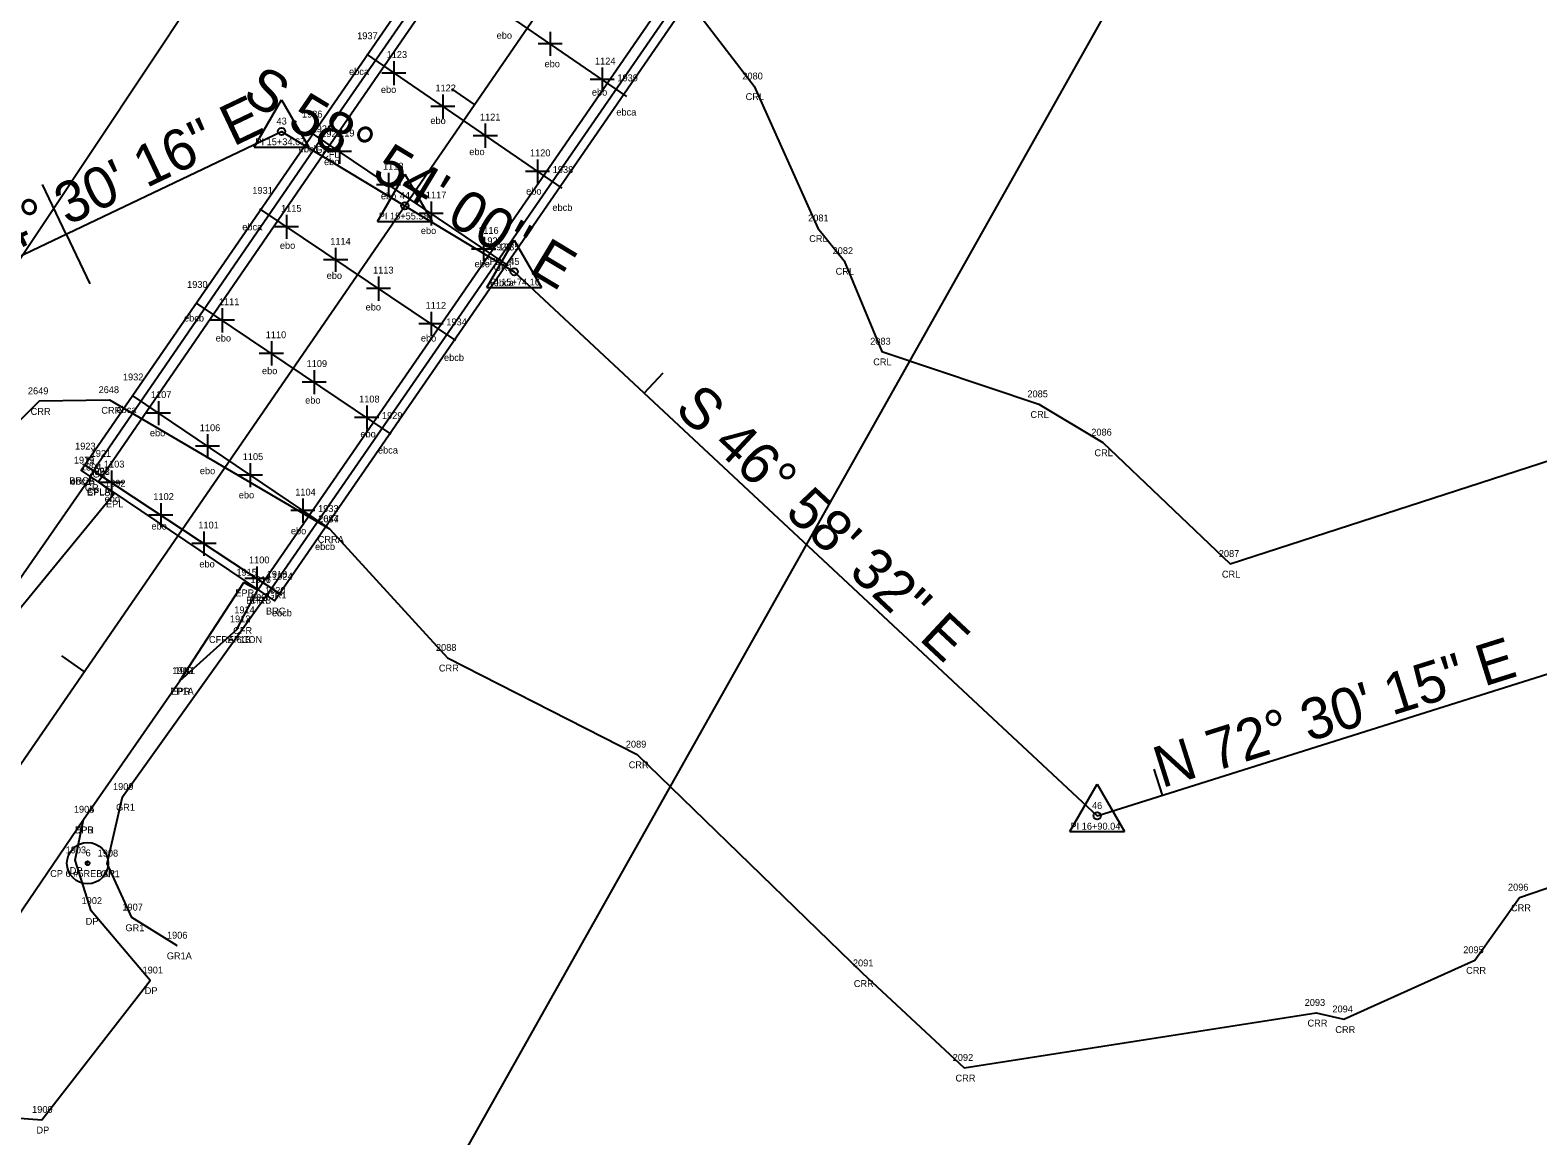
# Model space of a CAD drawing. Extents: x 2266664 to 2272542, y 716533 to 724777.
# Drawn here: x 2269953.4 to 2270172.5, y 721208.7 to 721369.4 of the extents above; entities that cross this region are included whole.
import ezdxf

# ---------------------------------------------------------------- set-up
doc = ezdxf.new("R2010")
doc.units = 0
for name, color, linetype in [('RD_EX_Bridge', 7, 'Continuous'), ('RD_EX_Bridge_txCode', 7, 'Continuous'), ('RD_EX_Conc', 7, 'Continuous'), ('RD_EX_Conc_txCode', 7, 'Continuous'), ('RD_EX_Driveway', 7, 'Continuous'), ('RD_EX_Driveway_txCode', 7, 'Continuous'), ('RD_EX_GuardRail', 7, 'Continuous'), ('RD_EX_GuardRail_txCode', 7, 'Continuous'), ('RD_EX_H2O', 7, 'Continuous'), ('RD_EX_H2O_txCode', 7, 'Continuous'), ('RD_EX_Misc', 7, 'Continuous'), ('RD_EX_Misc_txCode', 7, 'Continuous'), ('RD_EX_Road', 7, 'Continuous'), ('RD_EX_Road_txCode', 7, 'Continuous'), ('RD_EX_VEG', 7, 'Continuous'), ('RD_HC_Cl', 7, 'Continuous'), ('RD_HC_Data', 7, 'Continuous'), ('RD_HC_Data_Tic', 7, 'Continuous'), ('RD_HC_txCode', 7, 'Continuous'), ('RD_SMD_Locator', 7, 'Continuous')]:
    doc.layers.add(name, color=color, linetype=linetype)

msp = doc.modelspace()

# ---------------------------------------------------------------- linework, layer by layer
at = {"layer": 'RD_EX_Bridge'}
msp.add_lwpolyline([(2269960.85, 721305.41), (2269988.95, 721286.47), (2270056.9, 721385.08), (2270029.02, 721404.36), (2269960.85, 721305.41)], dxfattribs=at)
at = {"layer": 'RD_EX_Conc'}
for points in [[(2269963.38, 721303.82), (2269997.07, 721352.85), (2270031.4, 721402.66), (2270033.2, 721405.68), (2270033.91, 721407.54)], [(2269983.54, 721282.33), (2269984.17, 721283.64), (2269986.54, 721288.04), (2270020.48, 721337.28), (2270054.42, 721386.58), (2270057.31, 721390.25), (2270060.54, 721392.95), (2270061.95, 721393.64)]]:
    msp.add_lwpolyline(points, dxfattribs=at)
at = {"layer": 'RD_EX_Driveway'}
msp.add_lwpolyline([(2269930.38, 721209.38), (2269942.85, 721211.94), (2269955.14, 721211.05), (2269970.87, 721231.31), (2269962.29, 721241.39), (2269959.97, 721248.76), (2269961.18, 721254.67)], dxfattribs=at)
at = {"layer": 'RD_EX_GuardRail'}
for points in [[(2269870.57, 721186.54), (2269949.59, 721286.31), (2269962.16, 721304.4), (2269963.29, 721306.38), (2269995.7, 721353.55), (2270029.01, 721401.69), (2270040.18, 721416.99), (2270068.93, 721465.92)], [(2269974.73, 721236.37), (2269968.22, 721240.45), (2269964.64, 721248.3), (2269966.87, 721257.97), (2269988.88, 721288.81), (2270021.75, 721336.4), (2270054.42, 721383.83), (2270066.31, 721401.03), (2270101.34, 721444.56)]]:
    msp.add_lwpolyline(points, dxfattribs=at)
at = {"layer": 'RD_EX_H2O'}
for points in [[(2270050.62, 721371.69), (2270058.64, 721361.22), (2270067.88, 721340.59), (2270071.72, 721335.84), (2270077.18, 721322.68), (2270100.02, 721315.03), (2270109.33, 721309.47), (2270127.84, 721291.83), (2270185.1, 721310.38), (2270243.87, 721304.44), (2270281.75, 721346.08), (2270379.45, 721379), (2270436.63, 721386.23), (2270462.17, 721399.02)], [(2269996.97, 721296.88), (2269965.03, 721315.64), (2269954.76, 721315.47), (2269929.78, 721290.65), (2269924.59, 721291.58), (2269907.47, 721298.96), (2269898.39, 721300.95), (2269889.07, 721317.1), (2269874.61, 721338.02), (2269854.27, 721369.2), (2269839.08, 721382.01), (2269832.71, 721368.75), (2269810.27, 721357.54), (2269761.21, 721366.63), (2269754.56, 721317.04), (2269765.82, 721305.79), (2269769.06, 721297.52)], [(2269996.97, 721296.88), (2270014.08, 721278.19), (2270041.67, 721264.13), (2270074.38, 721232.34), (2270089.16, 721218.61), (2270140.31, 721226.6), (2270144.35, 721225.65), (2270163.36, 721234.25), (2270169.88, 721243.35), (2270177.39, 721245.92), (2270182.44, 721236.62), (2270238.2, 721231.39), (2270303.78, 721285.16), (2270310.34, 721288.45), (2270391.6, 721320.78), (2270477.31, 721344.54)]]:
    msp.add_lwpolyline(points, dxfattribs=at)
at = {"layer": 'RD_EX_Misc'}
for p, q in [((2270040.13, 721359.75), (2270011.59, 721379.34)), ((2270030.75, 721367.39), (2270027.25, 721367.39)), ((2270029, 721369.14), (2270029, 721365.64)), ((2270002.31, 721365.87), (2270030.72, 721346.42)), ((2270008.05, 721363.14), (2270004.55, 721363.14)), ((2270006.3, 721364.89), (2270006.3, 721361.39)), ((2270036.58, 721363.94), (2270036.58, 721360.44)), ((2270038.33, 721362.19), (2270034.83, 721362.19)), ((2270013.4, 721360.03), (2270013.4, 721356.53)), ((2270015.15, 721358.28), (2270011.65, 721358.28)), ((2270022.91, 721335.17), (2269994.31, 721354.48)), ((2270021.33, 721354.05), (2270017.83, 721354.05)), ((2270019.58, 721355.8), (2270019.58, 721352.3)), ((2269998.37, 721353.48), (2269998.37, 721349.98)), ((2270000.12, 721351.73), (2269996.62, 721351.73)), ((2270027.18, 721350.6), (2270027.18, 721347.1)), ((2270005.5, 721348.67), (2270005.5, 721345.17)), ((2270028.93, 721348.85), (2270025.43, 721348.85)), ((2270007.25, 721346.92), (2270003.75, 721346.92)), ((2269986.79, 721343.4), (2270015.26, 721324.29)), ((2270011.72, 721344.48), (2270011.72, 721340.98)), ((2269990.68, 721342.54), (2269990.68, 721339.04)), ((2270013.47, 721342.73), (2270009.97, 721342.73)), ((2269992.43, 721340.79), (2269988.93, 721340.79)), ((2270019.34, 721339.33), (2270019.34, 721335.83)), ((2269997.83, 721337.75), (2269997.83, 721334.25)), ((2270021.09, 721337.58), (2270017.59, 721337.58)), ((2269999.58, 721336), (2269996.08, 721336)), ((2270004.05, 721333.57), (2270004.05, 721330.07)), ((2270005.8, 721331.82), (2270002.3, 721331.82)), ((2270005.91, 721310.68), (2269977.63, 721329.73)), ((2269981.36, 721328.97), (2269981.36, 721325.47)), ((2270011.69, 721328.44), (2270011.69, 721324.94)), ((2269983.11, 721327.22), (2269979.61, 721327.22)), ((2270013.44, 721326.69), (2270009.94, 721326.69)), ((2269988.49, 721324.17), (2269988.49, 721320.67)), ((2269990.24, 721322.42), (2269986.74, 721322.42)), ((2269994.71, 721319.98), (2269994.71, 721316.48)), ((2269996.46, 721318.23), (2269992.96, 721318.23)), ((2269968.27, 721316.29), (2269996.62, 721297.16)), ((2269972.09, 721315.47), (2269972.09, 721311.97)), ((2270002.34, 721314.83), (2270002.34, 721311.33)), ((2269973.84, 721313.72), (2269970.34, 721313.72)), ((2270004.09, 721313.08), (2270000.59, 721313.08)), ((2269979.22, 721310.66), (2269979.22, 721307.16)), ((2269980.97, 721308.91), (2269977.47, 721308.91)), ((2269961.32, 721306.24), (2269989.97, 721287.33)), ((2269985.43, 721306.46), (2269985.43, 721302.96)), ((2269967.02, 721303.63), (2269963.52, 721303.63)), ((2269965.27, 721305.38), (2269965.27, 721301.88)), ((2269987.18, 721304.71), (2269983.68, 721304.71)), ((2269972.44, 721300.65), (2269972.44, 721297.15)), ((2269994.81, 721299.56), (2269991.31, 721299.56)), ((2269993.06, 721301.31), (2269993.06, 721297.81)), ((2269974.19, 721298.9), (2269970.69, 721298.9)), ((2269978.7, 721296.52), (2269978.7, 721293.02)), ((2269980.45, 721294.77), (2269976.95, 721294.77)), ((2269986.38, 721291.45), (2269986.38, 721287.95)), ((2269988.13, 721289.7), (2269984.63, 721289.7))]:
    msp.add_line(p, q, dxfattribs=at)
at = {"layer": 'RD_EX_Road'}
msp.add_line((2269975.2, 721274.82), (2269983.54, 721282.33), dxfattribs=at)
for points in [[(2269202.93, 720196.07), (2269237.22, 720244.72), (2269259.4, 720276.99), (2269259.41, 720277.21), (2269317.32, 720361.94), (2269369.05, 720437.36), (2269428.45, 720522.87), (2269487.41, 720608.15), (2269502.81, 720630.76), (2269544.96, 720692.14), (2269605.63, 720780.46), (2269663.95, 720865.82), (2269721.16, 720948.73), (2269780.45, 721034.57), (2269834.47, 721112.56), (2269853.48, 721140.68), (2269880.91, 721180.54), (2269894.87, 721200.75), (2269951.76, 721285.08), (2269965.67, 721302.04), (2269963.39, 721303.74)], [(2269222.47, 720182.37), (2269278.1, 720262.57), (2269277.83, 720263.03), (2269337.43, 720348.71), (2269393.72, 720430.44), (2269448.55, 720510.19), (2269506.62, 720593.92), (2269564.83, 720678.53), (2269625.78, 720767.57), (2269683.68, 720852.02), (2269741.8, 720936.18), (2269800.12, 721020.89), (2269854.32, 721099.54), (2269879.26, 721135.52), (2269912.84, 721184.64), (2269930.38, 721209.38), (2269961.18, 721254.67), (2269975.2, 721274.82), (2269984.48, 721289.11), (2269986.54, 721288.04)]]:
    msp.add_lwpolyline(points, dxfattribs=at)
at = {"layer": 'RD_EX_VEG'}
for points in [[(2268819.78, 719716.8), (2268871.54, 719776.21), (2269193.85, 720224.65), (2269408.57, 720538.5), (2269589.67, 720791.77), (2270047.56, 721479.8), (2270363.13, 721951.09), (2270746.65, 722498.38), (2270919.94, 722752.82), (2271017.26, 722923.37)], [(2269982.26, 721145.34), (2270153.55, 721449.76), (2270271.14, 721618.55), (2270388.14, 721782.77), (2270502.37, 721950.48), (2270556.28, 722038.41)]]:
    msp.add_lwpolyline(points, dxfattribs=at)
at = {"layer": 'RD_HC_Cl'}
for p, q in [((2267342.91, 717471.2), (2272360.46, 724762.59)), ((2269938.69, 721330.21), (2269989.98, 721354.67)), ((2269989.98, 721354.67), (2270023.79, 721334.28)), ((2270023.79, 721334.28), (2270108.5, 721255.21)), ((2270108.5, 721255.21), (2270181.25, 721278.14))]:
    msp.add_line(p, q, dxfattribs=at)
at = {"layer": 'RD_HC_Data'}
for p, q in [((2269986.01, 721352.38), (2269989.98, 721359.26)), ((2269989.98, 721359.26), (2269993.95, 721352.38)), ((2269986.01, 721352.38), (2269993.95, 721352.38)), ((2270003.91, 721341.58), (2270007.88, 721348.46)), ((2270007.88, 721348.46), (2270011.85, 721341.58)), ((2270003.91, 721341.58), (2270011.85, 721341.58)), ((2270019.82, 721331.98), (2270023.79, 721338.86)), ((2270023.79, 721338.86), (2270027.76, 721331.98)), ((2270019.82, 721331.98), (2270027.76, 721331.98)), ((2270104.53, 721252.92), (2270108.5, 721259.8)), ((2270108.5, 721259.8), (2270112.47, 721252.92)), ((2270104.53, 721252.92), (2270112.47, 721252.92))]:
    msp.add_line(p, q, dxfattribs=at)
for centre, radius in [((2269989.98, 721354.67), 0.529), ((2270007.88, 721343.87), 0.529), ((2270023.79, 721334.28), 0.529), ((2270108.5, 721255.21), 0.529), ((2269961.79, 721248.33), 3), ((2269961.79, 721248.33), 0.282)]:
    msp.add_circle(centre, radius, dxfattribs=at)
at = {"layer": 'RD_HC_Data_Tic'}
for p, q in [((2270018, 721358.59), (2270014.71, 721360.85)), ((2269958.68, 721339.75), (2269955.24, 721346.97)), ((2269958.68, 721339.75), (2269962.12, 721332.53)), ((2270042.68, 721316.64), (2270045.41, 721319.57)), ((2269961.31, 721276.21), (2269958.02, 721278.48)), ((2270118, 721258.21), (2270116.8, 721262.02))]:
    msp.add_line(p, q, dxfattribs=at)
at = {"layer": 'RD_SMD_Locator'}
for centre in [(2270058.64, 721361.22), (2269989.98, 721354.67), (2269995.7, 721353.55), (2269997.07, 721352.85), (2270007.88, 721343.87), (2270067.88, 721340.59), (2270020.48, 721337.28), (2270021.75, 721336.4), (2270071.72, 721335.84), (2270023.79, 721334.28), (2270077.18, 721322.68), (2269954.76, 721315.47), (2269965.03, 721315.64), (2270100.02, 721315.03), (2270109.33, 721309.47), (2269963.29, 721306.38), (2269960.85, 721305.41), (2269960.85, 721305.41), (2269962.16, 721304.4), (2269963.38, 721303.82), (2269963.39, 721303.74), (2269965.67, 721302.04), (2269996.97, 721296.88), (2269996.97, 721296.88), (2270127.84, 721291.83), (2269984.48, 721289.11), (2269988.88, 721288.81), (2269986.54, 721288.04), (2269986.54, 721288.04), (2269988.95, 721286.47), (2269983.54, 721282.33), (2269983.54, 721282.33), (2269984.17, 721283.64), (2270014.08, 721278.19), (2269975.2, 721274.82), (2269975.2, 721274.82), (2270041.67, 721264.13), (2269966.87, 721257.97), (2269961.18, 721254.67), (2269961.18, 721254.67), (2270108.5, 721255.21), (2269959.97, 721248.76), (2269961.79, 721248.33), (2269964.64, 721248.3), (2270169.88, 721243.35), (2269962.29, 721241.39), (2269968.22, 721240.45), (2269974.73, 721236.37), (2270163.36, 721234.25), (2270074.38, 721232.34), (2269970.87, 721231.31), (2270140.31, 721226.6), (2270144.35, 721225.65), (2270089.16, 721218.61), (2269955.14, 721211.05)]:
    msp.add_circle(centre, 0.001, dxfattribs=at)

# ---------------------------------------------------------------- texts
at = {"layer": 'RD_EX_Bridge_txCode'}
for s, p in [('1919', (2269959.79, 721306.41)), ('1971', (2269959.79, 721306.41)), ('BRCA', (2269959.11, 721303.41)), ('BRCB', (2269959.13, 721303.41)), ('1920', (2269987.57, 721287.47)), ('BRC', (2269987.7, 721284.47))]:
    msp.add_text(s, height=1, dxfattribs=at).set_placement(p)
at = {"layer": 'RD_EX_Conc_txCode'}
for s, p in [('1925', (2269995.73, 721353.85)), ('CFL', (2269995.87, 721350.85)), ('1927', (2270019.13, 721338.28)), ('CFR', (2270019.25, 721335.28)), ('1922', (2269962.04, 721304.82)), ('CFLA', (2269961.69, 721301.82)), ('1917', (2269985.47, 721289.04)), ('CFR', (2269985.31, 721286.04)), ('1913', (2269982.47, 721283.33)), ('1914', (2269983.1, 721284.64)), ('CFR', (2269982.94, 721281.64)), ('CFRA 6CON', (2269979.43, 721280.33))]:
    msp.add_text(s, height=1, dxfattribs=at).set_placement(p)
at = {"layer": 'RD_EX_Driveway_txCode'}
for s, p in [('1904', (2269959.79, 721255.67)), ('DPB', (2269959.92, 721252.67)), ('1903', (2269958.59, 721249.76)), ('DP', (2269959.19, 721246.76)), ('1902', (2269960.91, 721242.39)), ('DP', (2269961.51, 721239.39)), ('1901', (2269969.77, 721232.31)), ('DP', (2269970.09, 721229.31)), ('1900', (2269953.72, 721212.05)), ('DP', (2269954.36, 721209.05))]:
    msp.add_text(s, height=1, dxfattribs=at).set_placement(p)
at = {"layer": 'RD_EX_GuardRail_txCode'}
for s, p in [('1926', (2269994.33, 721354.55)), ('GR', (2269994.92, 721351.55)), ('1928', (2270020.41, 721337.4)), ('GR1', (2270020.81, 721334.4)), ('1921', (2269962.23, 721307.38)), ('1894', (2269960.82, 721305.4)), ('GR', (2269962.51, 721304.38)), ('GR', (2269961.39, 721302.4)), ('1918', (2269987.82, 721289.81)), ('GR1', (2269987.94, 721286.81)), ('1909', (2269965.48, 721258.97)), ('GR1', (2269965.92, 721255.97)), ('1908', (2269963.25, 721249.3)), ('GR1', (2269963.7, 721246.3)), ('1907', (2269966.84, 721241.45)), ('GR1', (2269967.28, 721238.45)), ('1906', (2269973.32, 721237.37)), ('GR1A', (2269973.29, 721234.37))]:
    msp.add_text(s, height=1, dxfattribs=at).set_placement(p)
at = {"layer": 'RD_EX_H2O_txCode'}
for s, p in [('2080', (2270056.93, 721362.22)), ('CRL', (2270057.41, 721359.22)), ('2081', (2270066.49, 721341.59)), ('CRL', (2270066.65, 721338.59)), ('2082', (2270070.05, 721336.84)), ('CRL', (2270070.49, 721333.84)), ('2083', (2270075.51, 721323.68)), ('CRL', (2270075.95, 721320.68)), ('2649', (2269953.11, 721316.47)), ('2648', (2269963.38, 721316.64)), ('2085', (2270098.36, 721316.03)), ('CRR', (2269963.78, 721313.64)), ('CRR', (2269953.51, 721313.47)), ('CRL', (2270098.8, 721313.03)), ('2086', (2270107.64, 721310.47)), ('CRL', (2270108.1, 721307.47)), ('2084', (2269995.3, 721297.88)), ('2647', (2269995.31, 721297.88)), ('CRRA', (2269995.23, 721294.88)), ('CRRA', (2269995.23, 721294.88)), ('2087', (2270126.17, 721292.83)), ('CRL', (2270126.62, 721289.83)), ('2088', (2270012.41, 721279.19)), ('CRR', (2270012.83, 721276.19)), ('2089', (2270040, 721265.13)), ('CRR', (2270040.42, 721262.13)), ('2096', (2270168.19, 721244.35)), ('CRR', (2270168.63, 721241.35)), ('2095', (2270161.69, 721235.25)), ('2091', (2270073, 721233.34)), ('CRR', (2270073.13, 721230.34)), ('CRR', (2270162.11, 721232.25)), ('2093', (2270138.65, 721227.6)), ('2094', (2270142.68, 721226.65)), ('CRR', (2270139.06, 721224.6)), ('CRR', (2270143.1, 721223.65)), ('2092', (2270087.5, 721219.61)), ('CRR', (2270087.91, 721216.61))]:
    msp.add_text(s, height=1, dxfattribs=at).set_placement(p)
at = {"layer": 'RD_EX_Misc_txCode'}
for s, p in [('1937', (2270000.96, 721368.07)), ('ebo', (2270021.23, 721368.13)), ('1123', (2270005.24, 721365.34)), ('ebo', (2270028.19, 721364)), ('1124', (2270035.52, 721364.39)), ('ebca', (2269999.78, 721362.87)), ('1939', (2270038.78, 721361.95)), ('ebo', (2270004.41, 721360.25)), ('1122', (2270012.33, 721360.48)), ('ebo', (2270035.07, 721359.87)), ('1936', (2269992.94, 721356.68)), ('ebo', (2270011.6, 721355.74)), ('1121', (2270018.8, 721356.25)), ('ebca', (2270038.62, 721356.98)), ('1119', (2269997.59, 721353.93)), ('ebcb', (2269992.47, 721351.62)), ('ebo', (2270017.25, 721351.22)), ('1120', (2270026.07, 721351.05)), ('ebo', (2269996.15, 721349.77)), ('1118', (2270004.72, 721349.12)), ('1938', (2270029.38, 721348.62)), ('1931', (2269985.73, 721345.6)), ('ebo', (2270004.41, 721344.8)), ('1117', (2270010.94, 721344.93)), ('ebo', (2270025.51, 721345.49)), ('1115', (2269989.9, 721342.99)), ('ebcb', (2270029.33, 721343.12)), ('ebca', (2269984.26, 721340.3)), ('1114', (2269997.05, 721338.2)), ('ebo', (2270010.22, 721339.75)), ('1116', (2270018.54, 721339.78)), ('ebo', (2269989.73, 721337.6)), ('1935', (2270021.56, 721337.37)), ('1113', (2270003.27, 721334.02)), ('ebo', (2270018.02, 721334.93)), ('1930', (2269976.25, 721331.93)), ('ebo', (2269996.53, 721333.24)), ('ebca', (2270020.81, 721332.19)), ('1111', (2269980.86, 721329.42)), ('ebcb', (2269975.8, 721327.05)), ('ebo', (2270002.19, 721328.65)), ('1112', (2270010.91, 721328.89)), ('1110', (2269987.67, 721324.62)), ('1934', (2270013.92, 721326.49)), ('ebo', (2269980.4, 721324.14)), ('ebo', (2270010.22, 721324.14)), ('1109', (2269993.61, 721320.43)), ('ebcb', (2270013.58, 721321.32)), ('1932', (2269966.92, 721318.49)), ('ebo', (2269987.13, 721319.39)), ('1107', (2269970.99, 721315.92)), ('ebca', (2269965.98, 721313.75)), ('ebo', (2269993.4, 721315.11)), ('1108', (2270001.24, 721315.28)), ('1929', (2270004.56, 721312.88)), ('ebo', (2269970.84, 721310.36)), ('1106', (2269978.09, 721311.11)), ('ebo', (2270001.43, 721310.21)), ('1923', (2269959.97, 721308.44)), ('ebca', (2270003.98, 721307.86)), ('1103', (2269964.16, 721305.83)), ('ebo', (2269978.1, 721304.86)), ('1105', (2269984.33, 721306.91)), ('ebca', (2269959.33, 721303.33)), ('ebo', (2269964.26, 721300.8)), ('1102', (2269971.34, 721301.1)), ('ebo', (2269983.76, 721301.34)), ('1104', (2269991.96, 721301.76)), ('1933', (2269995.28, 721299.36)), ('ebo', (2269971.07, 721296.82)), ('1101', (2269977.88, 721296.97)), ('ebo', (2269991.33, 721296.13)), ('ebcb', (2269994.84, 721293.85)), ('1100', (2269985.24, 721291.9)), ('ebo', (2269978.03, 721291.31)), ('1924', (2269988.62, 721289.53)), ('ebo', (2269985.52, 721286.64)), ('ebcb', (2269988.57, 721284.2))]:
    msp.add_text(s, height=1, dxfattribs=at).set_placement(p)
at = {"layer": 'RD_EX_Road_txCode'}
for s, p in [('1893', (2269962.04, 721304.74)), ('1892', (2269964.32, 721303.04)), ('EPLB', (2269961.71, 721301.74)), ('EPL', (2269964.47, 721300.04)), ('1915', (2269983.41, 721290.11)), ('1916', (2269985.45, 721289.04)), ('EPR', (2269983.25, 721287.11)), ('EPRB', (2269984.83, 721286.04)), ('1912', (2269982.47, 721283.33)), ('EP1B', (2269982.14, 721280.33)), ('1910', (2269974.09, 721275.82)), ('1911', (2269974.42, 721275.82)), ('EP1A', (2269973.79, 721272.82)), ('EPR', (2269973.97, 721272.82)), ('1905', (2269959.79, 721255.67)), ('EPR', (2269959.95, 721252.67))]:
    msp.add_text(s, height=1, dxfattribs=at).set_placement(p)
at = {"layer": 'RD_HC_Data'}
for s, rotation, p in [('S 58%%d 54\' 00" E', 328.9001, (2269984.07, 721359.4)), ('N 64%%d 30\' 16" E', 25.4954, (2269938.65, 721331.3)), ('S 46%%d 58\' 32" E', 316.9756, (2270046.91, 721314.06)), ('N 72%%d 30\' 15" E', 17.4959, (2270117.89, 721259.22))]:
    msp.add_text(s, height=6, rotation=rotation, dxfattribs=at).set_placement(p)
at = {"layer": 'RD_HC_txCode'}
for s, p in [('43', (2269989.24, 721355.67)), ('PI 15+34.67', (2269986.17, 721352.67)), ('44', (2270007.15, 721344.87)), ('PI 15+55.58', (2270004.1, 721341.87)), ('45', (2270023.06, 721335.28)), ('PI 15+74.16', (2270020.27, 721332.28)), ('46', (2270107.74, 721256.21)), ('PI 16+90.04', (2270104.62, 721253.21)), ('6', (2269961.49, 721249.33)), ('CP 6 #5REBAR', (2269956.35, 721246.33))]:
    msp.add_text(s, height=1, dxfattribs=at).set_placement(p)

doc.saveas('drawing.dxf')
